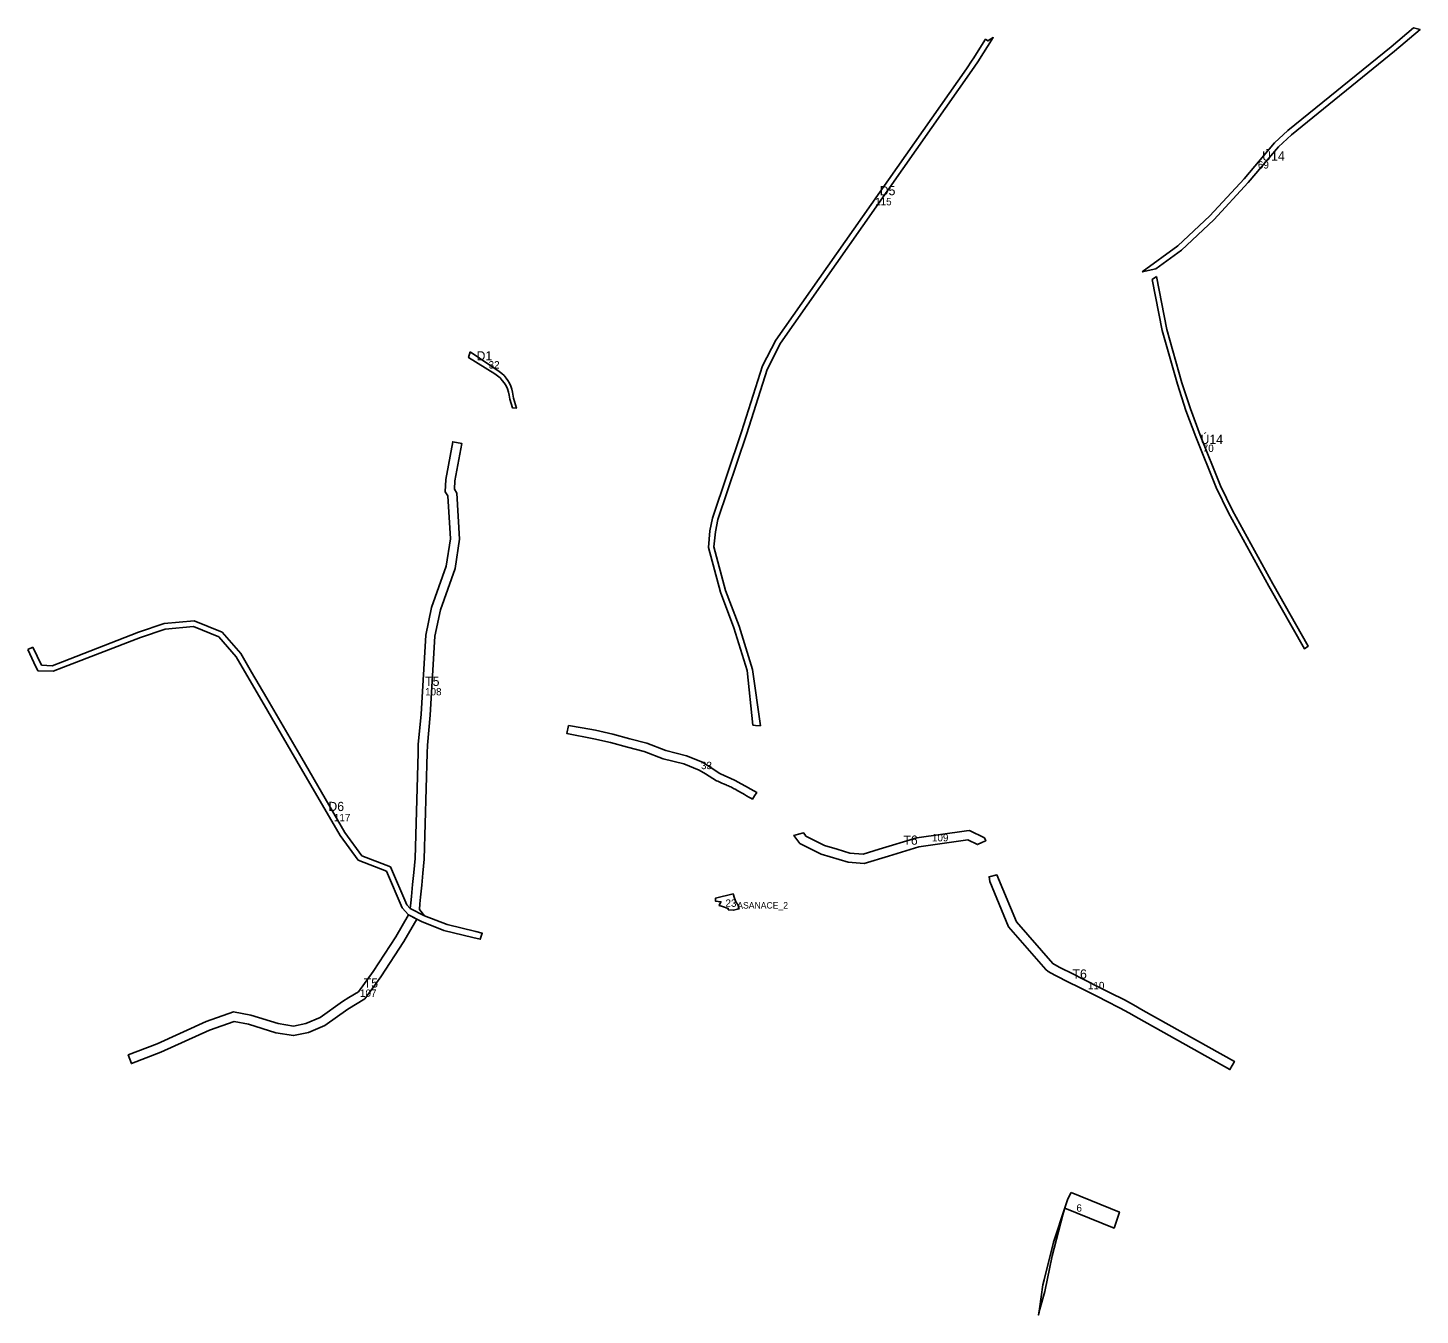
# Model space of a CAD drawing. Extents: x -521621 to -516857, y -1190025 to -1185894.
# Drawn here: x -519434 to -517922, y -1187292 to -1185894 of the extents above; entities that cross this region are included whole.
import ezdxf

# ---------------------------------------------------------------- set-up
doc = ezdxf.new("R2010")
doc.units = 0
for name, color, linetype in [('A_id', 7, 'Continuous'), ('asanace_n', 7, 'Continuous'), ('Implicitní', 7, 'Continuous'), ('predk_pravo_n', 7, 'Continuous'), ('VPO_id', 7, 'Continuous'), ('VPO_n', 7, 'Continuous'), ('VPS_id', 7, 'Continuous'), ('VPS_n', 7, 'Continuous')]:
    doc.layers.add(name, color=color, linetype=linetype)

msp = doc.modelspace()

# ---------------------------------------------------------------- linework, layer by layer
at = {"layer": 'Implicitní'}
msp.add_lwpolyline([(-518668.5, -1186834.7), (-518687.6, -1186839.4), (-518687.5, -1186842.8), (-518681.8, -1186843.4), (-518683.5, -1186847.6), (-518680, -1186848.7), (-518673.8, -1186850.6), (-518673.8, -1186852.1), (-518668, -1186852.7), (-518665, -1186851.9), (-518662, -1186851.2), (-518663.2, -1186846.4), (-518665.3, -1186844.4), (-518666.9, -1186839.5), (-518668.5, -1186834.7)], dxfattribs=at)
at = {"layer": 'predk_pravo_n'}
msp.add_lwpolyline([(-518677.4, -1186706.7), (-518682.8, -1186704.3), (-518692.2, -1186698), (-518701.7, -1186691.8), (-518719.2, -1186684.8), (-518741.4, -1186679.2), (-518762.3, -1186671.2), (-518780.7, -1186666.3), (-518799.2, -1186661.4), (-518808.6, -1186659.3), (-518817.9, -1186657.2), (-518832.6, -1186654.6), (-518847.2, -1186652.1), (-518849, -1186660.7), (-518819.9, -1186666.5), (-518801.5, -1186670.6), (-518783.2, -1186675.5), (-518765.2, -1186680.3), (-518744.3, -1186688.3), (-518722.1, -1186693.8), (-518705.3, -1186700.6), (-518698.6, -1186704.6), (-518686.4, -1186712), (-518685, -1186712.6), (-518683.6, -1186713.2), (-518682.2, -1186713.8), (-518680.8, -1186714.5), (-518678.8, -1186715.3), (-518676.2, -1186716.4), (-518674.8, -1186717.1), (-518673.5, -1186717.6), (-518672.3, -1186718.1), (-518671.1, -1186718.7), (-518669.8, -1186719.2), (-518667.3, -1186720.7), (-518666.4, -1186721.2), (-518665.7, -1186721.6), (-518664, -1186722.5), (-518662, -1186723.7), (-518660, -1186724.8), (-518658, -1186726), (-518656, -1186727.1), (-518653.8, -1186728.4), (-518651.5, -1186729.7), (-518649.3, -1186731), (-518647.5, -1186732), (-518645.1, -1186728.5), (-518642.8, -1186724.9), (-518645.9, -1186723.1), (-518649.1, -1186721.3), (-518655, -1186717.9), (-518659.8, -1186715.2), (-518666.1, -1186711.6), (-518671.8, -1186709.1), (-518677.4, -1186706.7)], dxfattribs=at)
msp.add_lwpolyline([(-518301.3, -1187159.1), (-518249, -1187180.4), (-518254.8, -1187197.9), (-518308.2, -1187176.1), (-518310.3, -1187183.3), (-518322, -1187228), (-518329.8, -1187266.7), (-518335.2, -1187285.8), (-518336.9, -1187292.4), (-518335.9, -1187285.7), (-518332, -1187259.4), (-518330.7, -1187254.1), (-518320.6, -1187213), (-518307.8, -1187174.6), (-518305, -1187166.2)], close=True, dxfattribs=at)
at = {"layer": 'VPO_n'}
for points in [[(-518224.3, -1186159.4), (-518185.4, -1186131.2), (-518150.7, -1186098.5), (-518113.5, -1186058.4), (-518080.5, -1186019.2), (-518066, -1186005.9), (-517953.9, -1185915), (-517929.5, -1185894.3), (-517922.3, -1185896.1), (-517950.1, -1185919.7), (-518062.1, -1186010.5), (-518076.2, -1186023.4), (-518109, -1186062.4), (-518146.4, -1186102.7), (-518181.5, -1186135.9), (-518209.5, -1186156.1)], [(-518208.8, -1186164.4), (-518197.5, -1186221.9), (-518181.1, -1186279.8), (-518171.9, -1186308.2), (-518161.3, -1186336.6), (-518139.2, -1186391.6), (-518126.2, -1186418.6), (-518082.2, -1186498.2), (-518043.9, -1186565.7), (-518048, -1186568.7), (-518086.6, -1186500.7), (-518130.6, -1186420.9), (-518143.7, -1186393.7), (-518166, -1186338.5), (-518176.7, -1186309.9), (-518185.9, -1186281.2), (-518202.4, -1186223.1), (-518213.3, -1186167.7)]]:
    msp.add_lwpolyline(points, close=True, dxfattribs=at)
at = {"layer": 'VPS_n'}
for points in [[(-518408.8, -1185929.5), (-518407.8, -1185928), (-518394.2, -1185906.7), (-518391.7, -1185908.5), (-518385.9, -1185904.8), (-518402.8, -1185931.3)], [(-518636.5, -1186261.5), (-518622.2, -1186233.6), (-518414.9, -1185939)], [(-518409.2, -1185940.6), (-518617, -1186236.6), (-518631.4, -1186265.3)], [(-518414.9, -1185939), (-518408.8, -1185929.5)], [(-518402.8, -1185931.3), (-518409.2, -1185940.6)], [(-518953.9, -1186246.2), (-518955.8, -1186252.5), (-518927.4, -1186270)], [(-518922.6, -1186267.6), (-518953.9, -1186246.2)], [(-518638.9, -1186652.2), (-518644, -1186652.1), (-518647, -1186651.6), (-518653.3, -1186592.2), (-518667.6, -1186545.9), (-518682.3, -1186507.3), (-518695.4, -1186458.6), (-518693.7, -1186440.7), (-518690.9, -1186426.8), (-518659.5, -1186333), (-518636.5, -1186261.5)], [(-518631.4, -1186265.3), (-518653.7, -1186334.8), (-518685.1, -1186428.3), (-518687.8, -1186441.6), (-518689.3, -1186458.1), (-518676.6, -1186505.5), (-518661.9, -1186544), (-518647.4, -1186591), (-518638.9, -1186652.2)], [(-518911.7, -1186293.4), (-518911, -1186297.5), (-518908.2, -1186306.9), (-518903.9, -1186307.5), (-518907.1, -1186296.6), (-518908.2, -1186290.1)], [(-519015.4, -1186811.5), (-519013.9, -1186796.5), (-519010.6, -1186681.7), (-519010.4, -1186672.8), (-519007.3, -1186639.8), (-519002.2, -1186553.8), (-518996.1, -1186523.7), (-518980.1, -1186479), (-518975.6, -1186449.1), (-518978.3, -1186402.7), (-518981.4, -1186398.1), (-518980.6, -1186385), (-518973, -1186343.9), (-518963.1, -1186345.8), (-518970.7, -1186386.2), (-518971.2, -1186395.4), (-518968.5, -1186399.5), (-518965.6, -1186449.6), (-518970.4, -1186481.5), (-518986.4, -1186526.4), (-518992.3, -1186555.1), (-518997.4, -1186640.6), (-519000.4, -1186673.4), (-519000.6, -1186682), (-519004, -1186797.1), (-519005.4, -1186812.4), (-519006.7, -1186825.4), (-519008, -1186838.6), (-519008.6, -1186845.6), (-519009.2, -1186851.7), (-519003.8, -1186858.7), (-519019.2, -1186850.6), (-519018.6, -1186844.6), (-519017.9, -1186837.7), (-519016.7, -1186824.5), (-519015.4, -1186811.5)], [(-519314.2, -1186550.8), (-519286.5, -1186541.3)], [(-519286.5, -1186541.3), (-519253.7, -1186538.2)], [(-519254.6, -1186544.3), (-519285.2, -1186547.2)], [(-519227.2, -1186555.7), (-519254.6, -1186544.3)], [(-519253.7, -1186538.2), (-519223.6, -1186550.7)], [(-519396.9, -1186582.8), (-519314.2, -1186550.8)], [(-519312.1, -1186556.4), (-519395.9, -1186588.8)], [(-519285.2, -1186547.2), (-519312.1, -1186556.4)], [(-519208.2, -1186577.3), (-519227.2, -1186555.7)], [(-519223.6, -1186550.7), (-519203.3, -1186573.7)], [(-519434.5, -1186569.6), (-519429.1, -1186567)], [(-519427.8, -1186583.6), (-519434.5, -1186569.6)], [(-519429.1, -1186567), (-519419.7, -1186586.6)], [(-519203.3, -1186573.7), (-519191.4, -1186594.2)], [(-519423.5, -1186592.5), (-519427.8, -1186583.6)], [(-519419.7, -1186586.6), (-519408, -1186587.1)], [(-519408, -1186587.1), (-519396.9, -1186582.8)], [(-519395.9, -1186588.8), (-519407, -1186593.1)], [(-519196.6, -1186597.2), (-519208.2, -1186577.3)], [(-519407, -1186593.1), (-519423.5, -1186592.5)], [(-519180.2, -1186625.3), (-519196.6, -1186597.2)], [(-519191.4, -1186594.2), (-519175, -1186622.3)], [(-519142.2, -1186690.6), (-519180.2, -1186625.3)], [(-519175, -1186622.3), (-519137, -1186687.6), (-519090.1, -1186768.1)], [(-519095.1, -1186771.4), (-519142.2, -1186690.6)], [(-519075.6, -1186798.4), (-519095.1, -1186771.4)], [(-519090.1, -1186768.1), (-519071.8, -1186793.4)], [(-518573, -1186791.7), (-518584.6, -1186785.9), (-518596.2, -1186780.1), (-518599.3, -1186775.7), (-518602.5, -1186771.3), (-518597.3, -1186770), (-518592, -1186768.7), (-518590.7, -1186770.5), (-518589.5, -1186772.2), (-518579.4, -1186777.3), (-518569.3, -1186782.3), (-518555.5, -1186786.4), (-518541.7, -1186790.6), (-518527.2, -1186791.6), (-518509.8, -1186786.4)], [(-518509.8, -1186786.4), (-518468.8, -1186774.1), (-518414.9, -1186766.3), (-518411.8, -1186765.9), (-518395.6, -1186774), (-518394.1, -1186777.2), (-518397.7, -1186778.8), (-518403.2, -1186781.3), (-518413.4, -1186776.2), (-518466.7, -1186783.9), (-518499.7, -1186793.8)], [(-519045, -1186810.3), (-519075.6, -1186798.4)], [(-519071.8, -1186793.4), (-519040.5, -1186805.6)], [(-518499.7, -1186793.8), (-518526.1, -1186801.7), (-518543.5, -1186800.4), (-518573, -1186791.7)], [(-519028, -1186850.1), (-519045, -1186810.3)], [(-519040.5, -1186805.6), (-519022.9, -1186846.8)], [(-519022.9, -1186846.8), (-519019.2, -1186850.6)], [(-519021, -1186857.6), (-519028, -1186850.1)], [(-519007, -1186864.9), (-519021, -1186857.6)], [(-519019.2, -1186850.6), (-519003.8, -1186858.7)], [(-519003.8, -1186858.7), (-518979.2, -1186868.2), (-518948, -1186875.8), (-518940.9, -1186877.6), (-518943.1, -1186884.1), (-518951.3, -1186882.1), (-518982.5, -1186874.5), (-519007, -1186864.9)]]:
    msp.add_lwpolyline(points, dxfattribs=at)
for points in [[(-518369.3, -1186870.6), (-518389.7, -1186821.6), (-518390.4, -1186816.3), (-518381.9, -1186814.2), (-518360.7, -1186865.2), (-518321.3, -1186910.5), (-518314.4, -1186914.4), (-518298.2, -1186922.5), (-518289.9, -1186926.7), (-518266.9, -1186938.3), (-518259.1, -1186942.2), (-518243.5, -1186950.1), (-518233.8, -1186955.5), (-518223, -1186961.5), (-518124.1, -1187016.9), (-518126.5, -1187021.3), (-518128.9, -1187025.6), (-518227.9, -1186970.3), (-518238.7, -1186964.2), (-518248.2, -1186958.9), (-518263.6, -1186951.1), (-518271.4, -1186947.2), (-518294.4, -1186935.6), (-518302.7, -1186931.4), (-518319.1, -1186923.2), (-518326.2, -1186919.2), (-518328.9, -1186917)], [(-519240.8, -1186973.6), (-519211.2, -1186963.1), (-519192.2, -1186966.6), (-519162.7, -1186975.8), (-519146.1, -1186978.5), (-519132.5, -1186975.8), (-519116.9, -1186969.1), (-519092.6, -1186951.6), (-519085.8, -1186947.5), (-519075.4, -1186941.1), (-519059.4, -1186919.2), (-519034.7, -1186881.5), (-519021, -1186857.6), (-519012.1, -1186862.2), (-519026.2, -1186886.7), (-519051.2, -1186924.9), (-519068.5, -1186948.7), (-519087.1, -1186960), (-519111.9, -1186977.9), (-519129.5, -1186985.4), (-519145.9, -1186988.7), (-519165, -1186985.6), (-519194.7, -1186976.3), (-519210.4, -1186973.4), (-519237, -1186982.9), (-519290, -1187006.8), (-519321.9, -1187019.1), (-519325.5, -1187009.8), (-519293.9, -1186997.6)]]:
    msp.add_lwpolyline(points, close=True, dxfattribs=at)
for centre, end in [((-518945.2, -1186299), 58.3971), ((-518941.7, -1186295.7), 55.7376)]:
    msp.add_arc(centre, 34, 9.5068, end, dxfattribs=at)

# ---------------------------------------------------------------- texts
at = {"layer": 'A_id'}
msp.add_text('23', height=8, dxfattribs=at).set_placement((-518676.8, -1186848.9))
at = {"layer": 'asanace_n'}
msp.add_text('ASANACE_2', height=7, dxfattribs=at).set_placement((-518664, -1186850.8))
at = {"layer": 'predk_pravo_n'}
for s, p in [('33', (-518703.4, -1186699.4)), ('6', (-518295.6, -1187180))]:
    msp.add_text(s, height=8, dxfattribs=at).set_placement(p)
at = {"layer": 'VPO_id'}
for s, p in [('69', (-518098.5, -1186047.1)), ('70', (-518158.4, -1186354.9))]:
    msp.add_text(s, height=8, dxfattribs=at).set_placement(p)
at = {"layer": 'VPO_n'}
for p in [(-518093.9, -1186038.5), (-518160.9, -1186346.2)]:
    msp.add_text('Ú14', height=10, dxfattribs=at).set_placement(p)
at = {"layer": 'VPS_id'}
for s, p in [('115', (-518514.2, -1186087)), ('32', (-518934, -1186264.3)), ('108', (-519003, -1186619.3)), ('117', (-519102, -1186756)), ('109', (-518452.5, -1186777.8)), ('107', (-519073.7, -1186946.7)), ('110', (-518283.1, -1186938.4))]:
    msp.add_text(s, height=8, dxfattribs=at).set_placement(p)
at = {"layer": 'VPS_n'}
for s, p in [('D5', (-518509.3, -1186076.1)), ('D1', (-518947.2, -1186255.5)), ('T5', (-519003, -1186609)), ('D6', (-519108.1, -1186744.9)), ('T6', (-518483.6, -1186781.5)), ('T6', (-518299.9, -1186926.9)), ('T5', (-519069.7, -1186936.6))]:
    msp.add_text(s, height=10, dxfattribs=at).set_placement(p)

doc.saveas('drawing.dxf')
